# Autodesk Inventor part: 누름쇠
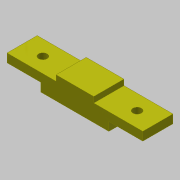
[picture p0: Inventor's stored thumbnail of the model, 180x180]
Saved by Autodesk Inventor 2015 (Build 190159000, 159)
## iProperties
Created: 2019-06
Part Number: 누름쇠
Material: 스테인리스강
Document SubType Name: Modeling
Designer: mduedu
Density: 1 g/cm^3
Appearance: 노란색
Author: mduedu
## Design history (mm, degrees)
sketch "스케치1"
  geometry: L1 (-36, 0)-(36, 0); L2 (36, 0)-(36, 12); L3 (36, 12)-(-36, 12); L4 (-36, 12)-(-36, 0); 2 further points
  constraints: 8 end point, 2 parallel, 1 coincident, 1 horizontal, 1 midpoint, 1 perpendicular
  dimensions: "d0" = 72 distance of L1.start L1.end; "d2" = 12 distance of L1.end L2.end
extrude "돌출1" new body sketch "스케치1" stored distance "d3" = 16; taper "d4" = 0 deg
sketch "스케치2"
  geometry: L1 (-36, 0)-(36, 0) reference; L2 (36, 0)-(36, 12) reference; L3 (36, 12)-(-36, 12) reference; L4 (-36, 12)-(-36, 0) reference; L5 (0, 0)-(0, 12); L6 (-36, 0)-(-18, 0); L7 (-18, 0)-(-18, 4.5); L8 (-18, 4.5)-(-36, 4.5); L9 (-36, 4.5)-(-36, 0); L10 (-36, 12)-(-10, 12); L11 (-10, 12)-(-10, 9); L12 (-10, 9)-(-36, 9); L13 (-36, 9)-(-36, 12); L14 (36, 12)-(36, 0); L15 (36, 0)-(18, 0); L16 (18, 0)-(18, 4.5); L17 (18, 4.5)-(36, 4.5); L18 (36, 4.5)-(36, 0); L19 (36, 12)-(10, 12); L20 (10, 12)-(10, 9); L21 (10, 9)-(36, 9); L22 (36, 9)-(36, 12)
  constraints: 36 end point, 6 symmetric about line, 4 parallel, 2 horizontal, 2 perpendicular, 1 midpoint
  dimensions: "d5" = 18 distance between parallel lines of L5 L7; "d7" = 4.5 distance between parallel lines of L1 L8; "d8" = 10 distance between parallel lines of L5 L11; "d9" = 3 distance between parallel lines of L12 L3
extrude "돌출2" cut sketch "스케치2" stored distance "d10" = 16; taper "d11" = 0 deg
sketch "스케치3"
  geometry: L1 (26, 0)-(26, 16) reference; L2 (0, 16)-(26, 16) reference; L3 (0, 0)-(0, 16) reference; L4 (26, 0)-(0, 0) reference; L5 (46, 0)-(26, 0) reference; L6 (46, 16)-(46, 0) reference; L7 (46, 16)-(72, 16) reference; L8 (72, 16)-(72, 0) reference; L9 (72, 0)-(46, 0) reference; L10 (26, 16)-(46, 16) reference; L11 (36, 16)-(36, 0); C1 r 2.25 at (11, 8); C2 r 2.25 at (61, 8); 1 further point
  constraints: 2 centre point, 2 end point, 2 midpoint, 1 horizontal alignment, 1 symmetric about line, 1 other
  dimensions: "d12" = 4.5 diameter of C1; "d13" = 25 distance of C1.centre point (36, 8)
extrude "돌출3" cut sketch "스케치3" stored distance "d14" = 16; taper "d15" = 0 deg
node "솔리드1"
node "투영된 루프1"
node "절단 모서리 투영1"
